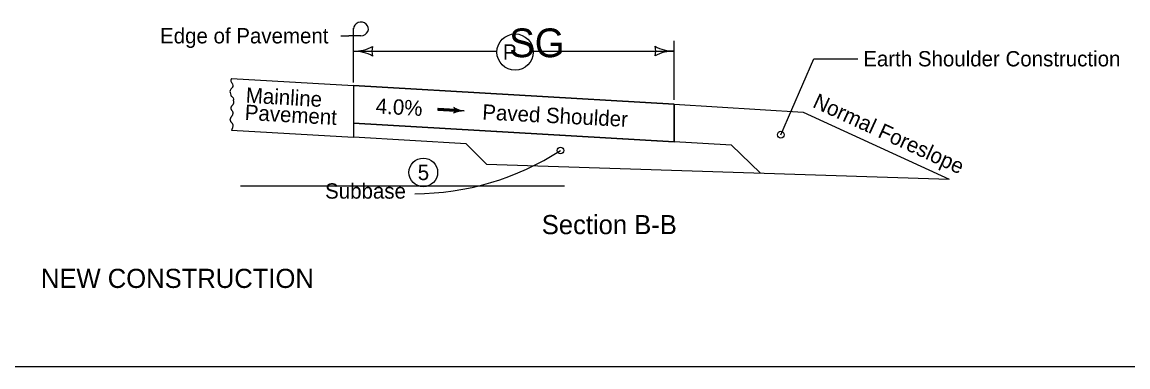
# Model space of a CAD drawing. Extents: x 9538 to 81668, y 7600 to 11751.
# Drawn here: x 11058 to 12213, y 8840 to 9200 of the extents above; entities that cross this region are included whole.
import ezdxf

# ---------------------------------------------------------------- set-up
doc = ezdxf.new("R2010")
doc.units = 0
for name, color, linetype in [('DsnShtMinorGrid13', 7, 'Continuous'), ('DsnShtMinorGrid14', 7, 'Continuous'), ('dsnStdDimension', 7, 'Continuous'), ('dsnStdNameDate', 7, 'Continuous'), ('dsnStdNote', 7, 'Continuous'), ('dsnStdTable', 7, 'Continuous')]:
    doc.layers.add(name, color=color, linetype=linetype)

msp = doc.modelspace()

# ---------------------------------------------------------------- linework, layer by layer
at = {"layer": 'DsnShtMinorGrid13'}
msp.add_circle((11477, 9043.2), 15, dxfattribs=at)
at = {"layer": 'DsnShtMinorGrid14'}
for centre in [(11850.7, 9082.6), (11620.4, 9066.1)]:
    msp.add_circle(centre, 3.54, dxfattribs=at)
at = {"layer": 'dsnStdDimension'}
for p, q in [((11739.2, 9119.1), (11739.2, 9180.8)), ((11404, 9169.8), (11554, 9169.8)), ((11591.8, 9170), (11739.2, 9170))]:
    msp.add_line(p, q, dxfattribs=at)
msp.add_circle((11572.9, 9169), 18.9, dxfattribs=at)
for centre, radius, start, end in [((11404, 9212.3), 42.5, 270, 298.0725), ((11404, 9127.3), 42.5, 61.9275, 90), ((11439.7, 9169.8), 16.4, 162.2666, 197.7334), ((11703.6, 9170), 16.4, 342.2666, 17.7333), ((11739.2, 9212.5), 42.5, 241.9275, 270), ((11739.2, 9127.5), 42.5, 90, 118.0725), ((11467.4, 9303), 282, 270.132, 302.8427)]:
    msp.add_arc(centre, radius, start, end, dxfattribs=at)
at = {"layer": 'dsnStdNameDate'}
for p, q in [((11739.2, 9114.6), (11404, 9134.1)), ((11404, 9134.1), (11404, 9094.5)), ((11739.2, 9075.1), (11739.2, 9114.6)), ((11404, 9094.5), (11739.2, 9075.1)), ((12303.1, 8840), (10147.5, 8840))]:
    msp.add_line(p, q, dxfattribs=at)
at = {"layer": 'dsnStdNote'}
for p, q in [((11404, 9173.1), (11404, 9194)), ((11390.7, 9186), (11399.3, 9186)), ((11411.8, 9186), (11399.3, 9186)), ((11404, 9137.2), (11404, 9173.1)), ((11850.7, 9082.6), (11885, 9162)), ((11885, 9162), (11931.3, 9162)), ((11510.4, 9108.1), (11492.2, 9109.1)), ((11510.3, 9107.1), (11510.3, 9107.1)), ((11510.4, 9109.1), (11510.4, 9109.1))]:
    msp.add_line(p, q, dxfattribs=at)
for points in [[(11510.4, 9109), (11492.3, 9110.1), (11492.1, 9108.2), (11510.3, 9107.1), (11510.4, 9108.8), (11492.5, 9109.9), (11492.4, 9108.4), (11509.9, 9107.4), (11510, 9108.5), (11492.7, 9109.6), (11492.7, 9108.6), (11509.7, 9107.6), (11509.8, 9108.3), (11492.9, 9109.4), (11492.9, 9108.8), (11509.5, 9107.9)], [(11510, 9110.3), (11510.7, 9109.1), (11510.7, 9107.5), (11509.9, 9106.1), (11512.7, 9106.9), (11515.9, 9107.6), (11516.8, 9107.7), (11514.5, 9108.3), (11511.3, 9109.5), (11510.4, 9110), (11510.5, 9106.5), (11515.4, 9107.7), (11510.8, 9109.3), (11510.8, 9106.9), (11514.2, 9107.8), (11511.2, 9108.7), (11511, 9107.3), (11513.1, 9107.8), (11511.6, 9108.3), (11511.4, 9107.7), (11512.2, 9107.8)]]:
    msp.add_lwpolyline(points, dxfattribs=at)
for centre, major_axis, start_param, end_param in [((11411.8, 9193.1), (-7.81, 0), 1.570796, 6.283185), ((11506.6, 9108.3), (3.88, 0), 5.202895, 7.237436), ((11518.9, 9087.3), (22.2, 0), 1.537172, 2.061295), ((11521.7, 9127.7), (-22.2, 0), 0.954258, 1.478381)]:
    msp.add_ellipse(centre, major_axis=major_axis, ratio=0.913811, start_param=start_param, end_param=end_param, dxfattribs=at)
at = {"layer": 'dsnStdTable'}
for p, q in [((11276.6, 9141.5), (11404, 9134.1)), ((11404, 9134.1), (11404, 9080)), ((11404, 9134.1), (11739.2, 9114.6)), ((11739.2, 9114.6), (11874, 9106.2)), ((11739.2, 9114.6), (11739.2, 9075.1)), ((11874, 9106.2), (12026.5, 9036.2)), ((11276.6, 9087.4), (11404, 9080)), ((11799.2, 9071.7), (11404, 9094.5)), ((11521.9, 9073.2), (11404, 9080)), ((11521.9, 9073.2), (11543.2, 9052)), ((11799.2, 9071.7), (11829, 9042.7)), ((11543.2, 9052), (12026.5, 9036.2)), ((11286, 9029.1), (11624.5, 9029.1))]:
    msp.add_line(p, q, dxfattribs=at)
for points in [[(11276.6, 9141.5), (11276.1, 9137.9), (11277.1, 9136.4), (11278, 9134.1), (11277.4, 9132), (11275.5, 9129.6), (11274.9, 9127.7), (11275.5, 9125.4), (11276.3, 9123), (11277.4, 9122.3), (11278.7, 9119.8), (11278.7, 9119)], [(11276.8, 9101.9), (11277, 9102.1), (11277.2, 9102.4), (11277.5, 9102.9), (11277.8, 9103.5), (11277.9, 9103.8), (11278, 9104.1), (11278.2, 9104.8), (11278.2, 9105.4), (11278.2, 9106), (11278.1, 9106.2), (11278.1, 9106.4), (11278, 9106.5), (11277.8, 9106.9), (11277.5, 9107.2), (11277.2, 9107.6), (11277, 9108), (11276.8, 9108.3), (11276.7, 9108.6), (11276.4, 9109.1), (11276.2, 9109.7), (11276.2, 9110), (11276.1, 9110.3), (11276.1, 9110.4), (11276.1, 9110.6), (11276.3, 9111.3), (11276.5, 9111.9), (11276.7, 9112.4), (11277.2, 9113), (11277.7, 9113.5), (11278.2, 9114.1), (11278.4, 9114.4), (11278.6, 9114.7), (11278.8, 9115.2), (11279, 9115.7), (11279.1, 9116.2), (11279.1, 9116.4), (11279.1, 9116.5), (11279.1, 9116.6), (11279.1, 9117.1), (11278.9, 9117.7), (11278.9, 9117.8), (11278.8, 9117.9), (11278.8, 9118), (11278.8, 9118.2), (11278.7, 9119)], [(11276.8, 9101.9), (11276.6, 9101.6), (11276.3, 9101.4), (11276.1, 9101.1), (11275.9, 9100.9), (11275.8, 9100.6), (11275.6, 9100.3), (11275.4, 9099.7), (11275.2, 9099.4), (11275.1, 9099.2), (11275.1, 9098.9), (11275, 9098.7), (11275, 9098.6), (11275, 9098.1), (11275.2, 9097.5), (11275.4, 9097), (11275.6, 9096.5), (11276.1, 9095.9), (11276.6, 9095.3), (11277.1, 9094.8), (11277.3, 9094.5), (11277.5, 9094.1), (11277.9, 9093.2), (11278, 9092.7), (11278.1, 9092.2), (11278, 9091.9), (11278, 9091.7), (11277.9, 9091.4), (11277.9, 9091.1), (11277.5, 9089.9), (11277.4, 9089.3), (11277.2, 9088.7), (11276.9, 9088.1), (11276.8, 9087.9), (11276.7, 9087.6), (11276.6, 9087.4)]]:
    msp.add_spline(points, degree=3, dxfattribs=at)

# ---------------------------------------------------------------- texts
at = {"layer": 'DsnShtMinorGrid13'}
msp.add_text('5', height=16, dxfattribs=at).set_placement((11471.2, 9035.2))
at = {"layer": 'dsnStdDimension'}
for s, height, p in [('SG', 30, (11566.7, 9163.6)), ('P', 16, (11560.2, 9161))]:
    msp.add_text(s, height=height, dxfattribs=at).set_placement(p)
at = {"layer": 'dsnStdNote'}
for s, height, p in [('Edge of Pavement', 16, (11201.9, 9178)), ('Earth Shoulder Construction', 16, (11936.8, 9154)), ('Subbase', 16, (11374.4, 9015.8)), ('Section B-B', 20, (11600.8, 8978.7)), ('NEW CONSTRUCTION', 20, (11077.4, 8922.5))]:
    msp.add_text(s, height=height, dxfattribs=at).set_placement(p)
for s, rotation, p in [('Mainline', 356.7346, (11291.2, 9116.1)), ('4.0%', 356.6992, (11427, 9104.9)), ('Normal Foreslope', 335.372, (11882.9, 9111.8)), ('Pavement', 356.7346, (11290.1, 9098.2)), ('Paved Shoulder ', 357.0678, (11538.4, 9098.5))]:
    msp.add_text(s, height=16, rotation=rotation, dxfattribs=at).set_placement(p)

doc.saveas('drawing.dxf')
